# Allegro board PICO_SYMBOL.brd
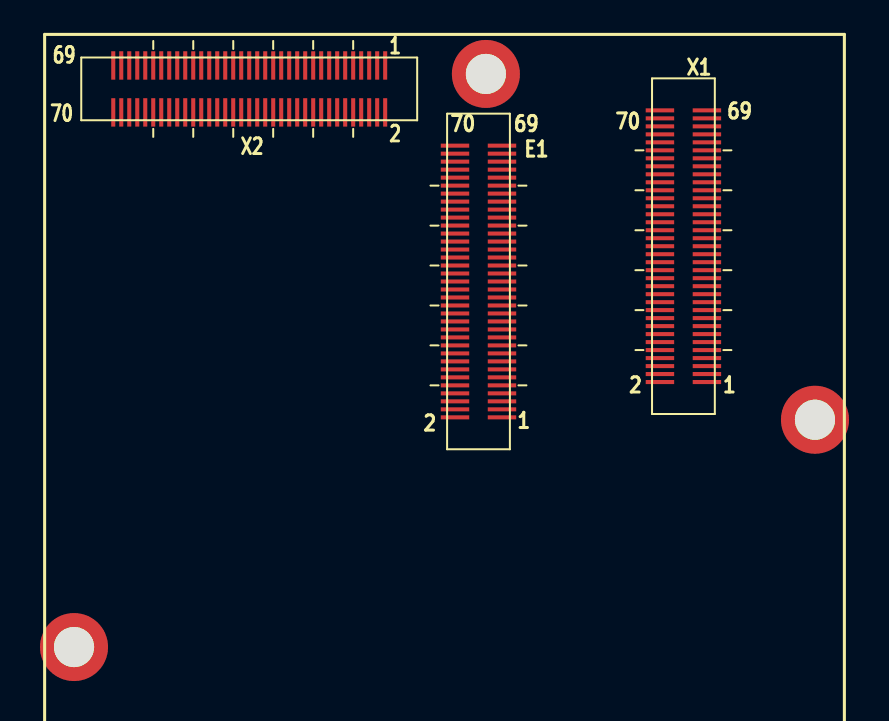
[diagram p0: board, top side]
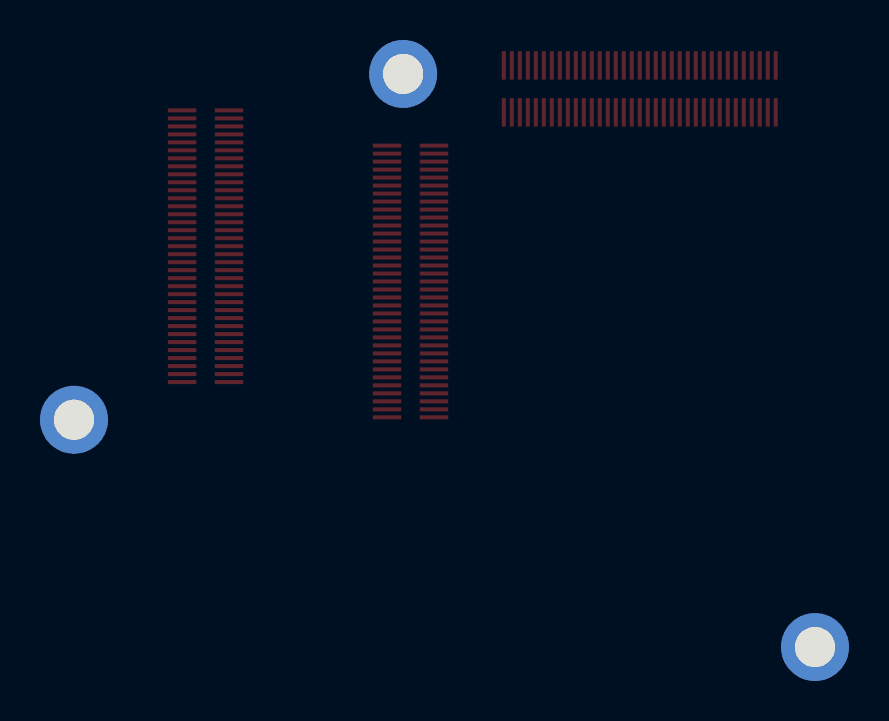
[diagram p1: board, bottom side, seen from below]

No outline. copper layers: TOP, GND, IN1, VCC, GND1, BOTTOM. Coordinates in mm from the lowest, leftmost part position.

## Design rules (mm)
net group GND: nets GND

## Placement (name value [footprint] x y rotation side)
E1  DF40HC(3.0)-70DS-0.4V(51)  [DF40HC-70DS-0D4V_RU]  22.5 42.61 270 top
HOLE4  NUT-50M30-501419D4BM-X  [MC134D79]  2.27 24.31 0 top
HOLE5  NUT-50M30-501419D4BM-X  [MC134D79]  22.87 53 0 top
HOLE6  NUT-50M30-501419D4BM-X  [MC134D79]  39.33 35.69 0 top
NOREF  -  []  0 6.99 0 top
NOREF#2  -  []  44.07 0 0 top
NOREF#3  -  []  0 6.99 0 top
X1  DF40HC(3.0)-70DS-0.4V(51)  [DF40HC-70DS-0D4V_RU]  32.75 44.38 270 top
X2  DF40HC(3.0)-70DS-0.4V(51)  [DF40HC-70DS-0D4V_RU]  11.03 52.25 0 top

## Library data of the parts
E1 X1 X2 = DF40HC-70DS-0D4V_RU
HOLE4-HOLE6 = MC134D79

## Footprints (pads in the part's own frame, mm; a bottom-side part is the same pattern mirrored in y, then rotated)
DF40HC-70DS-0D4V_RU
  rect 0.203x1.422 smd: 1(6.8,1.175) 2(6.8,-1.175) 3(6.4,1.175) 4(6.4,-1.175) 5(6,1.175) 6(6,-1.175) 7(5.6,1.175) 8(5.6,-1.175) 9(5.2,1.175) 10(5.2,-1.175) 11(4.8,1.175) 12(4.8,-1.175) 13(4.4,1.175) 14(4.4,-1.175) 15(4,1.175) 16(4,-1.175) 17(3.6,1.175) 18(3.6,-1.175) 19(3.2,1.175) 20(3.2,-1.175) 21(2.8,1.175) 22(2.8,-1.175) 23(2.4,1.175) 24(2.4,-1.175) 25(2,1.175) 26(2,-1.175) 27(1.6,1.175) 28(1.6,-1.175) 29(1.2,1.175) 30(1.2,-1.175) 31(0.8,1.175) 32(0.8,-1.175) 33(0.4,1.175) 34(0.4,-1.175) 35(0,1.175) 36(0,-1.175) 37(-0.4,1.175) 38(-0.4,-1.175) 39(-0.8,1.175) 40(-0.8,-1.175) 41(-1.2,1.175) 42(-1.2,-1.175) 43(-1.6,1.175) 44(-1.6,-1.175) 45(-2,1.175) 46(-2,-1.175) 47(-2.4,1.175) 48(-2.4,-1.175) 49(-2.8,1.175) 50(-2.8,-1.175) 51(-3.2,1.175) 52(-3.2,-1.175) 53(-3.6,1.175) 54(-3.6,-1.175) 55(-4,1.175) 56(-4,-1.175) 57(-4.4,1.175) 58(-4.4,-1.175) 59(-4.8,1.175) 60(-4.8,-1.175) 61(-5.2,1.175) 62(-5.2,-1.175) 63(-5.6,1.175) 64(-5.6,-1.175) 65(-6,1.175) 66(-6,-1.175) 67(-6.4,1.175) 68(-6.4,-1.175) 69(-6.8,1.175) 70(-6.8,-1.175)
MC134D79
  round 3.404 hole 2.007: 1(0,0)

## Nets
GND: HOLE4.1 HOLE5.1 HOLE6.1

Pads without a net: E1 1 2 3 4 5 6 7 8 9 10 11 12 13 14 15 16 17 18 19 20 21 22 23 24 25 26 27 28 29 30 31 32 33 34 35 36 37 38 39 40 41 42 43 44 45 46 47 48 49 50 51 52 53 54 55 56 57 58 59 60 61 62 63 64 65 66 67 68 69 70; X1 1 2 3 4 5 6 7 8 9 10 11 12 13 14 15 16 17 18 19 20 21 22 23 24 25 26 27 28 29 30 31 32 33 34 35 36 37 38 39 40 41 42 43 44 45 46 47 48 49 50 51 52 53 54 55 56 57 58 59 60 61 62 63 64 65 66 67 68 69 70; X2 1 2 3 4 5 6 7 8 9 10 11 12 13 14 15 16 17 18 19 20 21 22 23 24 25 26 27 28 29 30 31 32 33 34 35 36 37 38 39 40 41 42 43 44 45 46 47 48 49 50 51 52 53 54 55 56 57 58 59 60 61 62 63 64 65 66 67 68 69 70

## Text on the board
User.11: FIGURE | SIZE | 12.0 | 14.0 | 16.0 | 28.0 | 36.0 | 40.0 | 41.0 | 63.0 | 79.0 | 22.0 | 26.0 | 47.0 | 51.0 | 106.0 | 128.0 | 30x18 | 20x43 | 24x47 | 60x20 | 20x60 | 37x26 | DRILL CHART: TOP to BOTTOM | ALL UNITS ARE IN MILS | PLATED | NON-PLATED | QTY | 664 | 192 | 23 | 32 | 10 | 4 | 2 | 3 | 1 | 6
